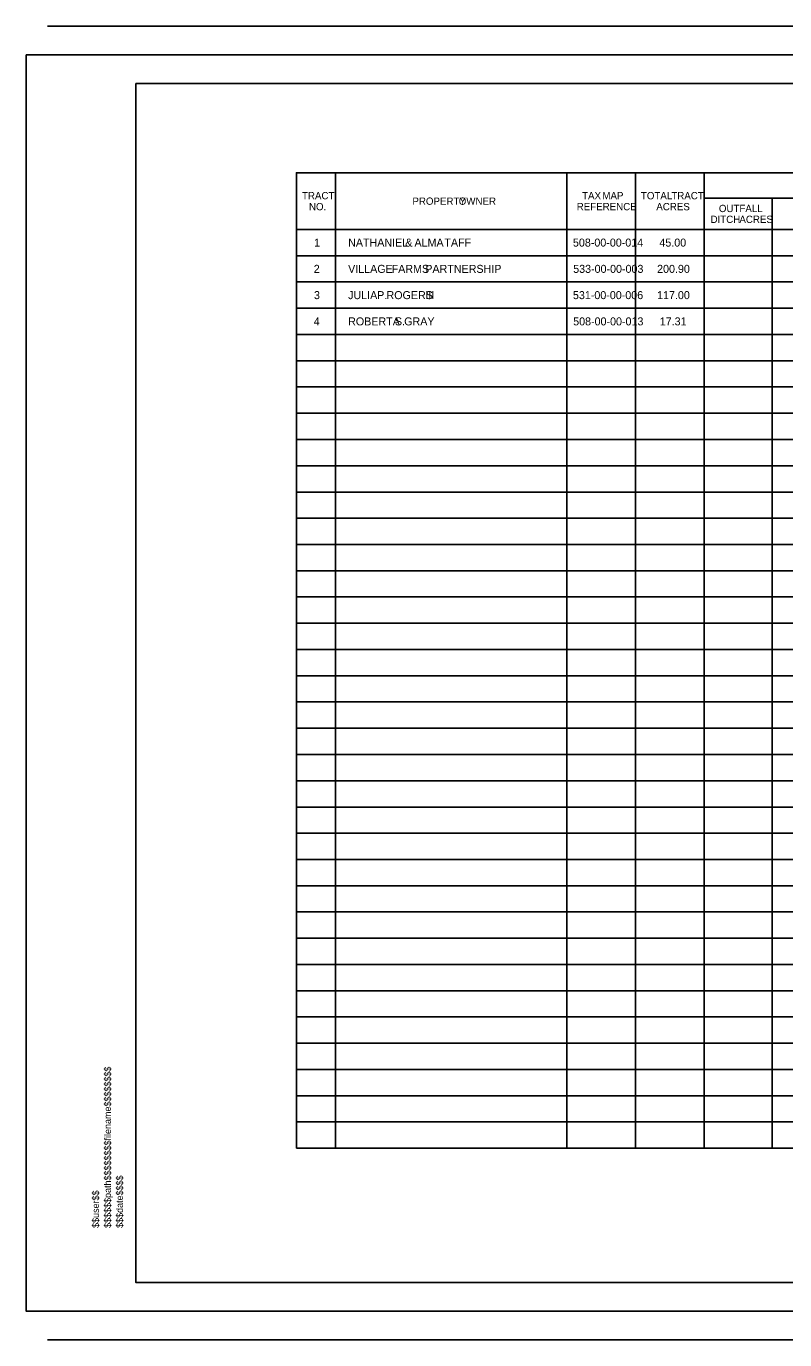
# Model space of a CAD drawing. Extents: x -19 to 1777, y -25 to 1125.
# Drawn here: x -19 to 646, y -25 to 1125 of the extents above; entities that cross this region are included whole.
import ezdxf

# ---------------------------------------------------------------- set-up
doc = ezdxf.new("R2010")
doc.units = 0
for name, color, linetype in [('RD_SHT_Bndy', 7, 'Continuous'), ('RD_SHT_ID', 7, 'Continuous'), ('RD_SHT_Iplotshp', 7, 'Continuous'), ('RD_SHT_MjGrid', 7, 'Continuous'), ('RD_TX_Misc1', 7, 'Continuous'), ('RD_TX_RW', 7, 'Continuous')]:
    doc.layers.add(name, color=color, linetype=linetype)

msp = doc.modelspace()

# ---------------------------------------------------------------- linework, layer by layer
at = {"layer": 'RD_SHT_Bndy'}
for p, q in [((0, 1125), (1760, 1125)), ((0, 1100), (1760, 1100)), ((0, 0), (1760, 0)), ((0, -25), (1760, -25))]:
    msp.add_line(p, q, dxfattribs=at)
for points in [[(77.4, 1075), (1752.4, 1075), (1752.4, 25), (77.4, 25)], [(218, 142.7), (1560.9, 142.7), (1560.9, 996.8), (218, 996.8)]]:
    msp.add_lwpolyline(points, close=True, dxfattribs=at)
at = {"layer": 'RD_SHT_Iplotshp'}
msp.add_lwpolyline([(-18.6, 1100), (1777.4, 1100), (1777.4, 0), (-18.6, 0)], close=True, dxfattribs=at)
at = {"layer": 'RD_SHT_MjGrid'}
for p, q in [((218, 996.8), (1560.9, 996.8)), ((218, 142.7), (218, 996.8)), ((252.2, 142.7), (252.2, 996.8)), ((454.7, 142.7), (454.7, 996.8)), ((514.9, 142.7), (514.9, 996.8)), ((575.2, 142.7), (575.2, 996.8)), ((575.2, 974.4), (813.7, 974.4)), ((634.8, 142.7), (634.8, 974.4)), ((218, 947.1), (1560.9, 947.1)), ((218, 924.1), (1560.9, 924.1)), ((218, 901.1), (1560.9, 901.1)), ((218, 878.1), (1560.9, 878.1)), ((218, 855.1), (1560.9, 855.1)), ((218, 832.1), (1560.9, 832.1)), ((218, 809.2), (1560.9, 809.2)), ((218, 786.2), (1560.9, 786.2)), ((218, 763.2), (1560.9, 763.2)), ((218, 740.2), (1560.9, 740.2)), ((218, 717.2), (1560.9, 717.2)), ((218, 694.3), (1560.9, 694.3)), ((218, 671.3), (1560.9, 671.3)), ((218, 648.3), (1560.9, 648.3)), ((218, 625.3), (1560.9, 625.3)), ((218, 602.3), (1560.9, 602.3)), ((218, 579.3), (1560.9, 579.3)), ((218, 556.4), (1560.9, 556.4)), ((218, 533.4), (1560.9, 533.4)), ((218, 510.4), (1560.9, 510.4)), ((218, 487.4), (1560.9, 487.4)), ((218, 464.4), (1560.9, 464.4)), ((218, 441.4), (1560.9, 441.4)), ((218, 418.5), (1560.9, 418.5)), ((218, 395.5), (1560.9, 395.5)), ((218, 372.5), (1560.9, 372.5)), ((218, 349.5), (1560.9, 349.5)), ((218, 326.5), (1560.9, 326.5)), ((218, 303.6), (1560.9, 303.6)), ((218, 280.6), (1560.9, 280.6)), ((218, 257.6), (1560.9, 257.6)), ((218, 234.6), (1560.9, 234.6)), ((218, 211.6), (1560.9, 211.6)), ((218, 188.6), (1560.9, 188.6)), ((218, 165.7), (1560.9, 165.7)), ((218, 142.7), (1560.9, 142.7))]:
    msp.add_line(p, q, dxfattribs=at)
at = {"layer": 'RD_TX_Misc1'}
msp.add_line((218, 996.8), (218, 996.8), dxfattribs=at)

# ---------------------------------------------------------------- texts
at = {"layer": 'RD_SHT_ID'}
for s, p in [('$$$$$$path$$$$$$$$filename$$$$$$$$', (55.6, 72.9)), ('$$$date$$$$', (66.1, 72.9)), ('$$user$$', (45.1, 72.9))]:
    msp.add_text(s, height=5.88, rotation=90, dxfattribs=at).set_placement(p)
at = {"layer": 'RD_TX_RW'}
for s, height, p in [('TRACT', 6.37, (222.9, 973.5)), ('TAX', 6.37, (468.2, 973.5)), (' MAP', 6.37, (483.6, 973.5)), ('TOTAL', 6.37, (519.7, 973.5)), (' TRACT', 6.37, (544, 973.5)), ('NO.', 6.37, (229, 963.9)), ('PROPERTY', 6.37, (319.6, 968.7)), (' OWNER', 6.37, (357.8, 968.7)), ('REFERENCE', 6.37, (463.5, 963.9)), ('ACRES', 6.37, (533.2, 963.9)), ('OUTFALL', 6.37, (588, 962.3)), ('DITCH', 6.37, (580.7, 952.8)), (' ACRES', 6.37, (603.6, 952.8)), ('1', 7.01, (233.5, 932.1)), ('NATHANIEL', 7.01, (263.3, 932.1)), (' &', 7.01, (310.7, 932.1)), (' ALMA', 7.01, (318.8, 932.1)), (' TAFF', 7.01, (345, 932.1)), ('508-00-00-014', 7.008, (460.2, 932.1)), ('45.00', 7.01, (535.9, 932.1)), ('2', 7.01, (233.2, 909.1)), ('VILLAGE', 7.01, (263.3, 909.1)), (' FARMS', 7.01, (298.8, 909.1)), (' PARTNERSHIP', 7.008, (328.3, 909.1)), ('533-00-00-003', 7.008, (460.4, 909.1)), ('200.90', 7.01, (533.9, 909.1)), ('3', 7.01, (233.4, 886.1)), ('JULIA', 7.01, (263.3, 886.1)), (' P.', 7.01, (286.1, 886.1)), (' ROGERS', 7.01, (294.3, 886.1)), (' III', 7.01, (328.3, 886.1)), ('531-00-00-006', 7.008, (460.2, 886.1)), ('117.00', 7.01, (533.9, 886.1)), ('4', 7.01, (233.2, 863.1)), ('ROBERTA', 7.01, (263.3, 863.1)), (' S.', 7.01, (301.7, 863.1)), (' GRAY', 7.01, (309.8, 863.1)), ('508-00-00-013', 7.008, (460.4, 863.1)), ('17.31', 7.01, (536.2, 863.1))]:
    msp.add_text(s, height=height, dxfattribs=at).set_placement(p)

doc.saveas('drawing.dxf')
